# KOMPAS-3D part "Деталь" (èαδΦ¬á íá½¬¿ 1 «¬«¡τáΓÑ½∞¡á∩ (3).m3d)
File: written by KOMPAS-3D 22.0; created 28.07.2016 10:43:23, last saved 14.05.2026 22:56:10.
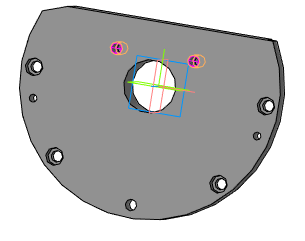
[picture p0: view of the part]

Document properties: Полное имя файла: E:\test_kompas\all_v20\Крышка балки 1 окончательная (3).m3d

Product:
- Part/product: Деталь
    Масса: 9.688835
- Part/product: Деталь  | designation 01
    Масса: 9.688835

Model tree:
1. Эскиз:1
2. Операция выдавливания:1
     Расстояние 1 = 40
3. Эскиз:2  (with: Операция выдавливания:1)
4. Элемент выдавливания:2
     Расстояние 2 = 20
5. Эскиз:13  (with: Операция выдавливания:1)
6. Элемент выдавливания:5
     Расстояние 2 = 40
7. Эскиз:14  (with: Операция выдавливания:1)
8. Эскиз:15  (with: Операция выдавливания:1, Элемент выдавливания:2)
9. Элемент выдавливания:6
     Расстояние 2 = 40
10. Эскиз:16  (with: Операция выдавливания:1, Элемент выдавливания:2)
11. Элемент выдавливания:7
     Расстояние 2 = 11
12. Отверстие:3  (with: Операция выдавливания:1)  (labels: M12)
     Глубина выреза = 30; Диаметр отверстия = 10.1056; Угол конуса дна = 118; Расстояние 1 = 31; Расстояние 2 = 46.4075
13. M12  (with: Отверстие:3, Операция выдавливания:1)  (labels: M12; cil0_24705-2004 coarse)
     Длина резьбы = 25; Шаг резьбы = 1.75; Номинальный диаметр резьбы = 12
14. Отверстие:4  (with: Операция выдавливания:1, M12)  (labels: M12; cil0_24705-2004 coarse)
     Глубина выреза = 30; Диаметр отверстия = 10.1056; Угол конуса дна = 118; Расстояние 1 = 31; Расстояние 2 = 70.8326; Длина резьбы = 25; Шаг резьбы = 1.75; Номинальный диаметр резьбы = 12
